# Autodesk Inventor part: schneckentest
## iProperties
Created: 2010-09
Part Number: schneckentest
Document SubType Name: Modeling
Designer: Löhr
Density: 1 g/cm^3
Author: Löhr
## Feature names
1. Extrusion1
2. Extrusion2
